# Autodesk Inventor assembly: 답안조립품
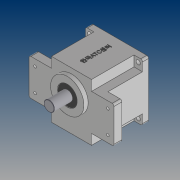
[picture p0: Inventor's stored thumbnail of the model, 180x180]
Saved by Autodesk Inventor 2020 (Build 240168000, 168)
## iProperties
Created: 2020-07
Part Number: 답안조립품
Document SubType Name: Assembly
Designer: PC312-02
Author: PC312-02
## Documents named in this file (10)
- C:\Users\PC312-02\Desktop\700718V1008\답안조립품.iam
- C:\Users\PC312-02\Desktop\700718V1008\본체.ipt
- C:\Users\PC312-02\Desktop\700718V1008\커버.ipt
- C:\Users\PC312-02\Desktop\700718V1008\베어링 6003.ipt
- C:\Users\PC312-02\Desktop\700718V1008\베어링 608.ipt
- C:\Users\PC312-02\Desktop\700718V1008\서브 축.ipt
- C:\Users\PC312-02\Desktop\700718V1008\메인 축.ipt
- C:\Users\PC312-02\Desktop\700718V1008\오일 실 8 22 7.ipt
- C:\Users\PC312-02\Desktop\700718V1008\오일 실 17 32 8.ipt
- C:\Users\PC312-02\Desktop\700718V1008\볼트 M4.ipt
